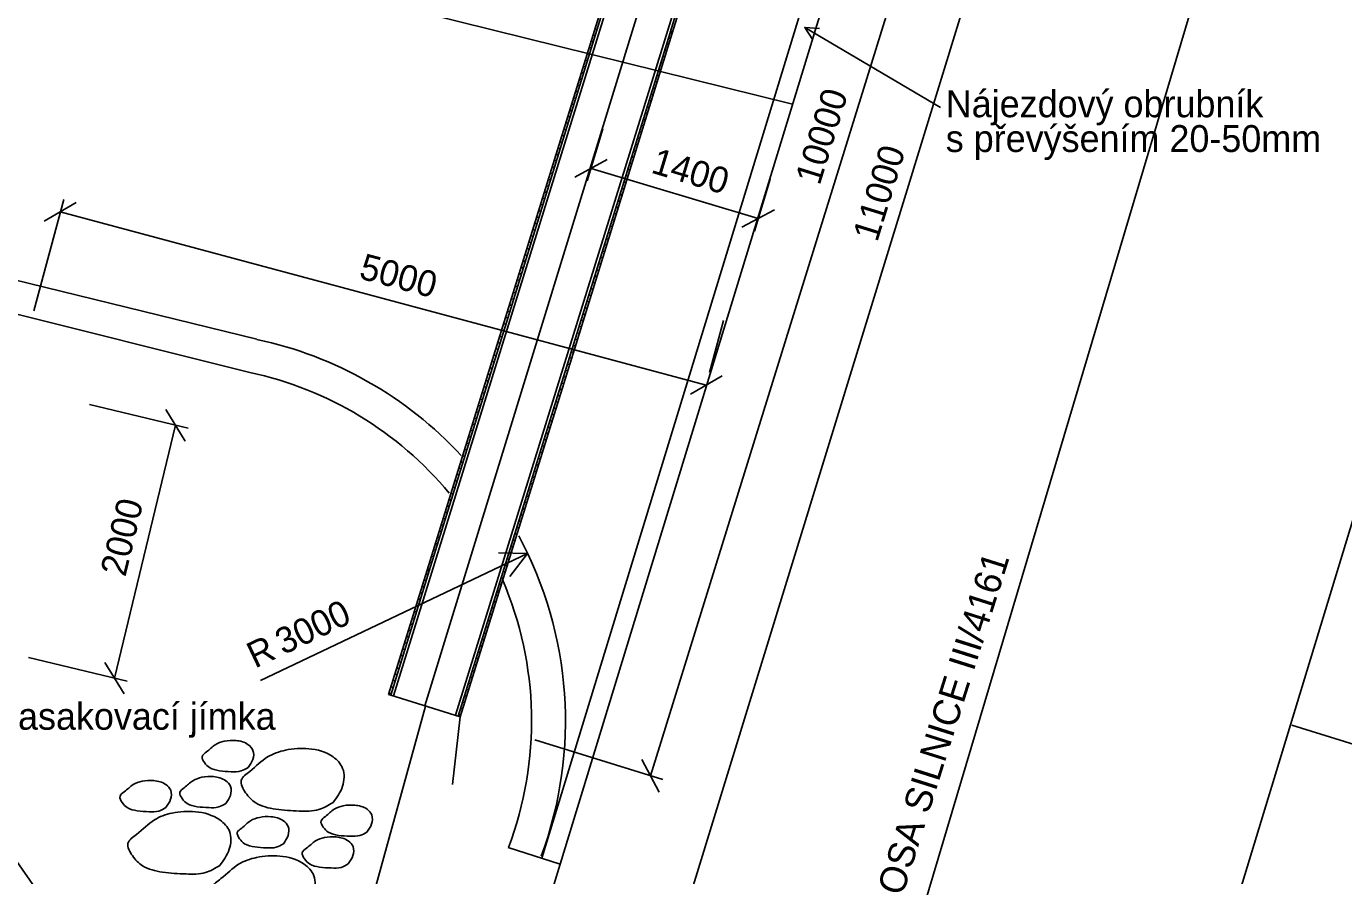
# Model space of a CAD drawing. Extents: x -577013.5 to -576971.5, y -1164310.3 to -1164280.6.
# Drawn here: x -576998.03 to -576987.9, y -1164300.03 to -1164293.5 of the extents above; entities that cross this region are included whole.
import ezdxf

# ---------------------------------------------------------------- set-up
doc = ezdxf.new("R2010")
doc.units = 0
for name, color, linetype in [('37', 7, 'Continuous'), ('5', 7, 'Continuous'), ('60', 7, 'Continuous'), ('61', 7, 'Continuous'), ('V_N1_detaily', 7, 'Continuous'), ('Vrstva 1', 7, 'Continuous'), ('Žlab', 7, 'Continuous')]:
    doc.layers.add(name, color=color, linetype=linetype)

msp = doc.modelspace()

# ---------------------------------------------------------------- linework, layer by layer
for p, q in [((-576992.94, -1164300.242), (-576989.668, -1164289.602)), ((-576993.228, -1164299.263), (-576990.265, -1164289.711)), ((-576993.593, -1164294.289), (-576993.714, -1164294.689)), ((-576993.809, -1164294.661), (-576993.56, -1164294.527)), ((-576992.4, -1164294.98), (-576993.685, -1164294.594)), ((-576992.308, -1164294.676), (-576992.428, -1164295.076)), ((-576997.97, -1164295.689), (-576997.74, -1164294.832)), ((-576997.889, -1164294.999), (-576997.644, -1164294.857)), ((-576997.766, -1164294.928), (-576992.799, -1164296.26)), ((-576992.275, -1164294.913), (-576992.524, -1164295.047)), ((-576996.255, -1164295.908), (-576998.747, -1164295.296)), ((-576996.309, -1164296.162), (-576998.962, -1164295.5)), ((-576992.666, -1164295.764), (-576992.773, -1164296.163)), ((-576992.676, -1164296.189), (-576992.921, -1164296.33)), ((-576997.542, -1164296.409), (-576996.783, -1164296.592)), ((-576996.954, -1164296.448), (-576996.807, -1164296.69)), ((-576997.349, -1164298.513), (-576996.88, -1164296.569)), ((-576994.173, -1164297.555), (-576996.226, -1164298.53)), ((-576998.011, -1164298.354), (-576997.252, -1164298.537)), ((-576997.276, -1164298.634), (-576997.423, -1164298.393)), ((-576994.751, -1164299.329), (-576994.69, -1164298.81)), ((-576996.082, -1164302.805), (-576998.818, -1164298.9)), ((-576994.117, -1164298.987), (-576993.132, -1164299.293)), ((-576993.162, -1164299.388), (-576993.294, -1164299.138)), ((-576993.922, -1164299.942), (-576994.321, -1164299.815))]:
    msp.add_line(p, q)
msp.add_lwpolyline([(-576994.396, -1164297.55), (-576994.173, -1164297.555), (-576994.31, -1164297.731)])
for radius, start, end in [(3, 42.8672, 77.9275), (2.74, 39.7281, 77.9275), (3, 339.7513, 28.3222), (2.74, 339.2034, 23.3649)]:
    msp.add_arc((-576996.882, -1164298.842), radius, start, end)
at = {"layer": '37'}
for p, q in [((-576990.807, -1164289.25), (-576994.063, -1164299.897)), ((-576990.666, -1164289.295), (-576993.922, -1164299.942)), ((-576990.056, -1164304.615), (-576986.686, -1164293.545)), ((-576993.922, -1164299.942), (-576996.088, -1164307.026))]:
    msp.add_line(p, q, dxfattribs=at)
at = {"layer": '5'}
msp.add_line((-576992.135, -1164294.101), (-577005.054, -1164290.899), dxfattribs=at)
at = {"layer": '60'}
msp.add_line((-576994.958, -1164298.727), (-576997.672, -1164308.563), dxfattribs=at)
at = {"layer": '61'}
msp.add_line((-576988.296, -1164298.875), (-576987.006, -1164299.275), dxfattribs=at)
at = {"layer": 'V_N1_detaily'}
for points in [[(-576996.322, -1164299.199), (-576996.376, -1164299.226), (-576996.452, -1164299.232), (-576996.542, -1164299.225), (-576996.619, -1164299.2), (-576996.658, -1164299.162), (-576996.675, -1164299.114), (-576996.642, -1164299.08), (-576996.574, -1164299.024), (-576996.505, -1164298.998), (-576996.415, -1164298.992), (-576996.321, -1164299.024), (-576996.285, -1164299.068), (-576996.285, -1164299.137), (-576996.322, -1164299.199)], [(-576995.669, -1164299.469), (-576995.778, -1164299.523), (-576995.929, -1164299.534), (-576996.109, -1164299.52), (-576996.263, -1164299.471), (-576996.341, -1164299.393), (-576996.375, -1164299.298), (-576996.309, -1164299.229), (-576996.172, -1164299.118), (-576996.035, -1164299.066), (-576995.856, -1164299.055), (-576995.668, -1164299.118), (-576995.595, -1164299.206), (-576995.596, -1164299.344), (-576995.669, -1164299.469)], [(-576996.954, -1164299.507), (-576997.009, -1164299.534), (-576997.084, -1164299.539), (-576997.174, -1164299.532), (-576997.251, -1164299.508), (-576997.29, -1164299.469), (-576997.307, -1164299.421), (-576997.274, -1164299.387), (-576997.206, -1164299.331), (-576997.137, -1164299.305), (-576997.048, -1164299.3), (-576996.954, -1164299.331), (-576996.917, -1164299.375), (-576996.918, -1164299.444), (-576996.954, -1164299.507)], [(-576996.494, -1164299.476), (-576996.548, -1164299.503), (-576996.624, -1164299.508), (-576996.714, -1164299.501), (-576996.791, -1164299.477), (-576996.83, -1164299.438), (-576996.847, -1164299.39), (-576996.814, -1164299.356), (-576996.746, -1164299.301), (-576996.677, -1164299.275), (-576996.588, -1164299.269), (-576996.494, -1164299.301), (-576996.457, -1164299.345), (-576996.458, -1164299.414), (-576996.494, -1164299.476)], [(-576996.54, -1164299.953), (-576996.649, -1164300.007), (-576996.799, -1164300.018), (-576996.98, -1164300.004), (-576997.134, -1164299.955), (-576997.212, -1164299.877), (-576997.246, -1164299.782), (-576997.18, -1164299.714), (-576997.043, -1164299.602), (-576996.906, -1164299.55), (-576996.727, -1164299.539), (-576996.539, -1164299.603), (-576996.465, -1164299.69), (-576996.467, -1164299.828), (-576996.54, -1164299.953)], [(-576995.408, -1164299.696), (-576995.462, -1164299.722), (-576995.538, -1164299.728), (-576995.628, -1164299.721), (-576995.705, -1164299.696), (-576995.744, -1164299.658), (-576995.761, -1164299.61), (-576995.728, -1164299.576), (-576995.66, -1164299.52), (-576995.591, -1164299.494), (-576995.502, -1164299.489), (-576995.407, -1164299.52), (-576995.371, -1164299.564), (-576995.372, -1164299.633), (-576995.408, -1164299.696)], [(-576996.051, -1164299.785), (-576996.106, -1164299.812), (-576996.181, -1164299.817), (-576996.271, -1164299.81), (-576996.349, -1164299.786), (-576996.388, -1164299.747), (-576996.405, -1164299.699), (-576996.371, -1164299.665), (-576996.303, -1164299.609), (-576996.234, -1164299.583), (-576996.145, -1164299.578), (-576996.051, -1164299.609), (-576996.014, -1164299.653), (-576996.015, -1164299.722), (-576996.051, -1164299.785)], [(-576995.552, -1164299.94), (-576995.607, -1164299.967), (-576995.682, -1164299.972), (-576995.772, -1164299.965), (-576995.849, -1164299.941), (-576995.888, -1164299.902), (-576995.905, -1164299.854), (-576995.872, -1164299.82), (-576995.804, -1164299.764), (-576995.735, -1164299.738), (-576995.646, -1164299.733), (-576995.552, -1164299.764), (-576995.515, -1164299.808), (-576995.516, -1164299.877), (-576995.552, -1164299.94)], [(-576995.891, -1164300.294), (-576996.001, -1164300.348), (-576996.151, -1164300.359), (-576996.331, -1164300.344), (-576996.486, -1164300.296), (-576996.564, -1164300.218), (-576996.597, -1164300.122), (-576996.531, -1164300.054), (-576996.395, -1164299.943), (-576996.257, -1164299.891), (-576996.079, -1164299.88), (-576995.891, -1164299.943), (-576995.817, -1164300.031), (-576995.819, -1164300.169), (-576995.891, -1164300.294)]]:
    msp.add_spline(points, degree=3, dxfattribs=at)
at = {"layer": 'Vrstva 1'}
for p, q in [((-576992.834, -1164306.008), (-576986.608, -1164285.099)), ((-576992.041, -1164293.511), (-576990.998, -1164294.126))]:
    msp.add_line(p, q, dxfattribs=at)
msp.add_lwpolyline([(-576991.98, -1164293.605), (-576992.041, -1164293.511), (-576991.929, -1164293.519)], dxfattribs=at)
at = {"layer": 'Žlab'}
for p, q in [((-576992.242, -1164289.098), (-576995.204, -1164298.649)), ((-576992.024, -1164289.166), (-576994.962, -1164298.726)), ((-576991.764, -1164289.246), (-576994.727, -1164298.797)), ((-576993.67, -1164293.569), (-576993.652, -1164293.572)), ((-576993.655, -1164293.521), (-576993.637, -1164293.523)), ((-576993.077, -1164293.551), (-576993.077, -1164293.551)), ((-576993.076, -1164293.55), (-576993.06, -1164293.555)), ((-576993.073, -1164293.539), (-576993.056, -1164293.542)), ((-576993.699, -1164293.665), (-576993.682, -1164293.668)), ((-576993.684, -1164293.617), (-576993.667, -1164293.62)), ((-576993.104, -1164293.638), (-576993.086, -1164293.641)), ((-576993.089, -1164293.59), (-576993.071, -1164293.592)), ((-576993.729, -1164293.762), (-576993.712, -1164293.765)), ((-576993.714, -1164293.714), (-576993.697, -1164293.716)), ((-576993.134, -1164293.734), (-576993.116, -1164293.737)), ((-576993.119, -1164293.686), (-576993.101, -1164293.689)), ((-576993.759, -1164293.858), (-576993.742, -1164293.861)), ((-576993.744, -1164293.81), (-576993.727, -1164293.813)), ((-576993.179, -1164293.879), (-576993.161, -1164293.882)), ((-576993.164, -1164293.831), (-576993.146, -1164293.834)), ((-576993.149, -1164293.783), (-576993.131, -1164293.785)), ((-576993.789, -1164293.955), (-576993.772, -1164293.958)), ((-576993.774, -1164293.907), (-576993.757, -1164293.909)), ((-576993.208, -1164293.976), (-576993.191, -1164293.978)), ((-576993.193, -1164293.927), (-576993.176, -1164293.93)), ((-576993.819, -1164294.052), (-576993.802, -1164294.054)), ((-576993.804, -1164294.003), (-576993.787, -1164294.006)), ((-576993.238, -1164294.072), (-576993.221, -1164294.075)), ((-576993.223, -1164294.024), (-576993.206, -1164294.027)), ((-576993.849, -1164294.148), (-576993.832, -1164294.151)), ((-576993.834, -1164294.1), (-576993.817, -1164294.102)), ((-576993.268, -1164294.169), (-576993.251, -1164294.171)), ((-576993.253, -1164294.12), (-576993.236, -1164294.123)), ((-576993.879, -1164294.245), (-576993.862, -1164294.247)), ((-576993.864, -1164294.196), (-576993.847, -1164294.199)), ((-576993.298, -1164294.265), (-576993.281, -1164294.268)), ((-576993.283, -1164294.217), (-576993.266, -1164294.22)), ((-576993.909, -1164294.341), (-576993.892, -1164294.344)), ((-576993.894, -1164294.293), (-576993.877, -1164294.296)), ((-576993.328, -1164294.362), (-576993.311, -1164294.365)), ((-576993.313, -1164294.314), (-576993.296, -1164294.316)), ((-576993.954, -1164294.486), (-576993.937, -1164294.489)), ((-576993.939, -1164294.438), (-576993.922, -1164294.44)), ((-576993.924, -1164294.389), (-576993.907, -1164294.392)), ((-576993.358, -1164294.458), (-576993.341, -1164294.461)), ((-576993.343, -1164294.41), (-576993.326, -1164294.413)), ((-576993.984, -1164294.582), (-576993.967, -1164294.585)), ((-576993.969, -1164294.534), (-576993.952, -1164294.537)), ((-576993.388, -1164294.555), (-576993.371, -1164294.558)), ((-576993.373, -1164294.507), (-576993.356, -1164294.509)), ((-576994.014, -1164294.679), (-576993.996, -1164294.682)), ((-576993.999, -1164294.631), (-576993.981, -1164294.633)), ((-576993.418, -1164294.651), (-576993.401, -1164294.654)), ((-576993.403, -1164294.603), (-576993.386, -1164294.606)), ((-576994.044, -1164294.776), (-576994.026, -1164294.778)), ((-576994.029, -1164294.727), (-576994.011, -1164294.73)), ((-576993.448, -1164294.748), (-576993.431, -1164294.751)), ((-576993.433, -1164294.7), (-576993.416, -1164294.702)), ((-576994.074, -1164294.872), (-576994.056, -1164294.875)), ((-576994.059, -1164294.824), (-576994.041, -1164294.827)), ((-576993.493, -1164294.893), (-576993.476, -1164294.895)), ((-576993.478, -1164294.845), (-576993.461, -1164294.847)), ((-576993.463, -1164294.796), (-576993.446, -1164294.799)), ((-576994.104, -1164294.969), (-576994.086, -1164294.971)), ((-576994.089, -1164294.92), (-576994.071, -1164294.923)), ((-576993.523, -1164294.989), (-576993.505, -1164294.992)), ((-576993.508, -1164294.941), (-576993.491, -1164294.944)), ((-576994.134, -1164295.065), (-576994.116, -1164295.068)), ((-576994.119, -1164295.017), (-576994.101, -1164295.02)), ((-576993.553, -1164295.086), (-576993.535, -1164295.089)), ((-576993.538, -1164295.038), (-576993.52, -1164295.04)), ((-576994.164, -1164295.162), (-576994.146, -1164295.164)), ((-576994.149, -1164295.113), (-576994.131, -1164295.116)), ((-576993.583, -1164295.182), (-576993.565, -1164295.185)), ((-576993.568, -1164295.134), (-576993.55, -1164295.137)), ((-576994.193, -1164295.258), (-576994.176, -1164295.261)), ((-576994.179, -1164295.21), (-576994.161, -1164295.213)), ((-576993.613, -1164295.279), (-576993.595, -1164295.282)), ((-576993.598, -1164295.231), (-576993.58, -1164295.233)), ((-576994.223, -1164295.355), (-576994.206, -1164295.357)), ((-576994.208, -1164295.306), (-576994.191, -1164295.309)), ((-576993.643, -1164295.375), (-576993.625, -1164295.378)), ((-576993.628, -1164295.327), (-576993.61, -1164295.33)), ((-576994.268, -1164295.5), (-576994.251, -1164295.502)), ((-576994.253, -1164295.451), (-576994.236, -1164295.454)), ((-576994.238, -1164295.403), (-576994.221, -1164295.406)), ((-576993.673, -1164295.472), (-576993.655, -1164295.475)), ((-576993.658, -1164295.424), (-576993.64, -1164295.426)), ((-576994.298, -1164295.596), (-576994.281, -1164295.599)), ((-576994.283, -1164295.548), (-576994.266, -1164295.551)), ((-576993.703, -1164295.569), (-576993.685, -1164295.571)), ((-576993.688, -1164295.52), (-576993.67, -1164295.523)), ((-576994.328, -1164295.693), (-576994.311, -1164295.695)), ((-576994.313, -1164295.644), (-576994.296, -1164295.647)), ((-576993.732, -1164295.665), (-576993.715, -1164295.668)), ((-576993.717, -1164295.617), (-576993.7, -1164295.619)), ((-576994.358, -1164295.789), (-576994.341, -1164295.792)), ((-576994.343, -1164295.741), (-576994.326, -1164295.744)), ((-576993.762, -1164295.762), (-576993.745, -1164295.764)), ((-576993.747, -1164295.713), (-576993.73, -1164295.716)), ((-576994.388, -1164295.886), (-576994.371, -1164295.888)), ((-576994.373, -1164295.837), (-576994.356, -1164295.84)), ((-576993.807, -1164295.906), (-576993.79, -1164295.909)), ((-576993.792, -1164295.858), (-576993.775, -1164295.861)), ((-576993.777, -1164295.81), (-576993.76, -1164295.813)), ((-576994.418, -1164295.982), (-576994.401, -1164295.985)), ((-576994.403, -1164295.934), (-576994.386, -1164295.937)), ((-576993.837, -1164296.003), (-576993.82, -1164296.006)), ((-576993.822, -1164295.955), (-576993.805, -1164295.957)), ((-576994.448, -1164296.079), (-576994.431, -1164296.081)), ((-576994.433, -1164296.03), (-576994.416, -1164296.033)), ((-576993.867, -1164296.099), (-576993.85, -1164296.102)), ((-576993.852, -1164296.051), (-576993.835, -1164296.054)), ((-576994.478, -1164296.175), (-576994.461, -1164296.178)), ((-576994.463, -1164296.127), (-576994.446, -1164296.13)), ((-576993.897, -1164296.196), (-576993.88, -1164296.199)), ((-576993.882, -1164296.148), (-576993.865, -1164296.15)), ((-576994.508, -1164296.272), (-576994.491, -1164296.275)), ((-576994.493, -1164296.224), (-576994.476, -1164296.226)), ((-576993.927, -1164296.293), (-576993.91, -1164296.295)), ((-576993.912, -1164296.244), (-576993.895, -1164296.247)), ((-576994.538, -1164296.368), (-576994.52, -1164296.371)), ((-576994.523, -1164296.32), (-576994.505, -1164296.323)), ((-576993.957, -1164296.389), (-576993.94, -1164296.392)), ((-576993.942, -1164296.341), (-576993.925, -1164296.343)), ((-576994.583, -1164296.513), (-576994.565, -1164296.516)), ((-576994.568, -1164296.465), (-576994.55, -1164296.468)), ((-576994.553, -1164296.417), (-576994.535, -1164296.419)), ((-576993.987, -1164296.486), (-576993.97, -1164296.488)), ((-576993.972, -1164296.437), (-576993.955, -1164296.44)), ((-576994.613, -1164296.61), (-576994.595, -1164296.612)), ((-576994.598, -1164296.561), (-576994.58, -1164296.564)), ((-576994.017, -1164296.582), (-576994, -1164296.585)), ((-576994.002, -1164296.534), (-576993.985, -1164296.537)), ((-576994.643, -1164296.706), (-576994.625, -1164296.709)), ((-576994.628, -1164296.658), (-576994.61, -1164296.661)), ((-576994.047, -1164296.679), (-576994.029, -1164296.681)), ((-576994.032, -1164296.63), (-576994.015, -1164296.633)), ((-576994.673, -1164296.803), (-576994.655, -1164296.805)), ((-576994.658, -1164296.755), (-576994.64, -1164296.757)), ((-576994.077, -1164296.775), (-576994.059, -1164296.778)), ((-576994.062, -1164296.727), (-576994.044, -1164296.73)), ((-576994.703, -1164296.899), (-576994.685, -1164296.902)), ((-576994.688, -1164296.851), (-576994.67, -1164296.854)), ((-576994.122, -1164296.92), (-576994.104, -1164296.923)), ((-576994.107, -1164296.872), (-576994.089, -1164296.874)), ((-576994.092, -1164296.823), (-576994.074, -1164296.826)), ((-576994.732, -1164296.996), (-576994.715, -1164296.999)), ((-576994.717, -1164296.948), (-576994.7, -1164296.95)), ((-576994.152, -1164297.017), (-576994.134, -1164297.019)), ((-576994.137, -1164296.968), (-576994.119, -1164296.971)), ((-576994.762, -1164297.092), (-576994.745, -1164297.095)), ((-576994.747, -1164297.044), (-576994.73, -1164297.047)), ((-576994.182, -1164297.113), (-576994.164, -1164297.116)), ((-576994.167, -1164297.065), (-576994.149, -1164297.068)), ((-576994.792, -1164297.189), (-576994.775, -1164297.192)), ((-576994.777, -1164297.141), (-576994.76, -1164297.143)), ((-576994.212, -1164297.21), (-576994.194, -1164297.212)), ((-576994.197, -1164297.161), (-576994.179, -1164297.164)), ((-576994.822, -1164297.285), (-576994.805, -1164297.288)), ((-576994.807, -1164297.237), (-576994.79, -1164297.24)), ((-576994.241, -1164297.306), (-576994.224, -1164297.309)), ((-576994.226, -1164297.258), (-576994.209, -1164297.261)), ((-576994.852, -1164297.382), (-576994.835, -1164297.385)), ((-576994.837, -1164297.334), (-576994.82, -1164297.336)), ((-576994.271, -1164297.403), (-576994.254, -1164297.405)), ((-576994.256, -1164297.354), (-576994.239, -1164297.357)), ((-576994.897, -1164297.527), (-576994.88, -1164297.529)), ((-576994.882, -1164297.479), (-576994.865, -1164297.481)), ((-576994.867, -1164297.43), (-576994.85, -1164297.433)), ((-576994.301, -1164297.499), (-576994.284, -1164297.502)), ((-576994.286, -1164297.451), (-576994.269, -1164297.454)), ((-576994.927, -1164297.623), (-576994.91, -1164297.626)), ((-576994.912, -1164297.575), (-576994.895, -1164297.578)), ((-576994.331, -1164297.596), (-576994.314, -1164297.598)), ((-576994.316, -1164297.547), (-576994.299, -1164297.55)), ((-576994.954, -1164297.711), (-576994.937, -1164297.714)), ((-576994.946, -1164297.683), (-576994.946, -1164297.683)), ((-576994.945, -1164297.683), (-576994.929, -1164297.688)), ((-576994.942, -1164297.672), (-576994.925, -1164297.674)), ((-576994.361, -1164297.692), (-576994.344, -1164297.695)), ((-576994.346, -1164297.644), (-576994.329, -1164297.647)), ((-576994.984, -1164297.807), (-576994.967, -1164297.81)), ((-576994.969, -1164297.759), (-576994.952, -1164297.762)), ((-576994.391, -1164297.789), (-576994.374, -1164297.792)), ((-576994.376, -1164297.741), (-576994.359, -1164297.743)), ((-576995.014, -1164297.904), (-576994.997, -1164297.907)), ((-576994.999, -1164297.856), (-576994.982, -1164297.858)), ((-576994.433, -1164297.925), (-576994.416, -1164297.927)), ((-576994.418, -1164297.876), (-576994.401, -1164297.879)), ((-576994.41, -1164297.848), (-576994.393, -1164297.853)), ((-576994.41, -1164297.849), (-576994.41, -1164297.849)), ((-576994.406, -1164297.837), (-576994.389, -1164297.84)), ((-576995.044, -1164298.001), (-576995.027, -1164298.003)), ((-576995.029, -1164297.952), (-576995.012, -1164297.955)), ((-576994.463, -1164298.021), (-576994.446, -1164298.024)), ((-576994.448, -1164297.973), (-576994.431, -1164297.976)), ((-576995.074, -1164298.097), (-576995.057, -1164298.1)), ((-576995.059, -1164298.049), (-576995.042, -1164298.051)), ((-576994.493, -1164298.118), (-576994.476, -1164298.12)), ((-576994.478, -1164298.069), (-576994.461, -1164298.072)), ((-576995.104, -1164298.194), (-576995.087, -1164298.196)), ((-576995.089, -1164298.145), (-576995.072, -1164298.148)), ((-576994.523, -1164298.214), (-576994.506, -1164298.217)), ((-576994.508, -1164298.166), (-576994.491, -1164298.169)), ((-576995.149, -1164298.338), (-576995.131, -1164298.341)), ((-576995.134, -1164298.29), (-576995.117, -1164298.293)), ((-576995.119, -1164298.242), (-576995.102, -1164298.245)), ((-576994.553, -1164298.311), (-576994.536, -1164298.314)), ((-576994.538, -1164298.263), (-576994.521, -1164298.265)), ((-576995.179, -1164298.435), (-576995.161, -1164298.438)), ((-576995.164, -1164298.387), (-576995.146, -1164298.389)), ((-576994.583, -1164298.407), (-576994.566, -1164298.41)), ((-576994.568, -1164298.359), (-576994.551, -1164298.362)), ((-576995.209, -1164298.531), (-576995.191, -1164298.534)), ((-576995.194, -1164298.483), (-576995.176, -1164298.486)), ((-576994.613, -1164298.504), (-576994.596, -1164298.507)), ((-576994.598, -1164298.456), (-576994.581, -1164298.458)), ((-576995.242, -1164298.639), (-576995.225, -1164298.644)), ((-576995.239, -1164298.628), (-576995.221, -1164298.631)), ((-576995.224, -1164298.58), (-576995.206, -1164298.582)), ((-576994.643, -1164298.6), (-576994.626, -1164298.603)), ((-576994.628, -1164298.552), (-576994.611, -1164298.555)), ((-576995.225, -1164298.644), (-576994.69, -1164298.81)), ((-576994.673, -1164298.697), (-576994.655, -1164298.7)), ((-576994.658, -1164298.649), (-576994.641, -1164298.651)), ((-576994.706, -1164298.804), (-576994.69, -1164298.81)), ((-576994.703, -1164298.793), (-576994.685, -1164298.796)), ((-576994.688, -1164298.745), (-576994.67, -1164298.748))]:
    msp.add_line(p, q, dxfattribs=at)
for points in [[(-576991.744, -1164289.253), (-576991.744, -1164289.253), (-576993.076, -1164293.55)], [(-576993.06, -1164293.555), (-576992.467, -1164291.645), (-576991.727, -1164289.257), (-576991.744, -1164289.253)], [(-576993.613, -1164293.385), (-576993.613, -1164293.385), (-576994.945, -1164297.683)], [(-576994.929, -1164297.688), (-576994.336, -1164295.778), (-576993.596, -1164293.39), (-576993.613, -1164293.385)], [(-576993.077, -1164293.551), (-576993.077, -1164293.551), (-576994.41, -1164297.848)], [(-576994.393, -1164297.853), (-576993.8, -1164295.943), (-576993.06, -1164293.555), (-576993.077, -1164293.551)], [(-576994.946, -1164297.683), (-576994.946, -1164297.683), (-576995.242, -1164298.639)], [(-576995.225, -1164298.644), (-576994.929, -1164297.688), (-576994.946, -1164297.683)], [(-576994.41, -1164297.849), (-576994.41, -1164297.849), (-576994.706, -1164298.804)], [(-576994.69, -1164298.81), (-576994.393, -1164297.853), (-576994.41, -1164297.849)]]:
    msp.add_lwpolyline(points, dxfattribs=at)

# ---------------------------------------------------------------- texts
for s, rotation, p in [('10000', 72.7677, (-576991.927, -1164294.731)), ('1400', 343.2677, (-576993.232, -1164294.625)), ('11000', 72.9031, (-576991.484, -1164295.167)), ('5000', 344.9953, (-576995.477, -1164295.438)), ('2000', 76.4371, (-576997.266, -1164297.74)), ('3000', 25.4103, (-576996.052, -1164298.337)), ('R', 25.4103, (-576996.269, -1164298.44))]:
    msp.add_text(s, height=0.2, rotation=rotation).set_placement(p)
at = {"layer": 'Vrstva 1'}
for s, p in [('Nájezdový obrubník ', (-576990.957, -1164294.201)), ('s převýšením 20-50mm', (-576990.957, -1164294.468)), ('Zasakovací jímka', (-576998.26, -1164298.909))]:
    msp.add_text(s, height=0.20663, dxfattribs=at).set_placement(p)
msp.add_text('OSA SILNICE III/4161', height=0.20663, rotation=72.4419, dxfattribs=at).set_placement((-576991.29, -1164300.194))

doc.saveas('drawing.dxf')
